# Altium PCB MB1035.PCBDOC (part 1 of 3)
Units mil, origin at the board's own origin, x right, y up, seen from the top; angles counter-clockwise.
Board outline 2598.43 x 3818.9 mil, 2 copper layers (TOP, Bottom); 145 components, 171 nets, 593 pads, 200 vias.
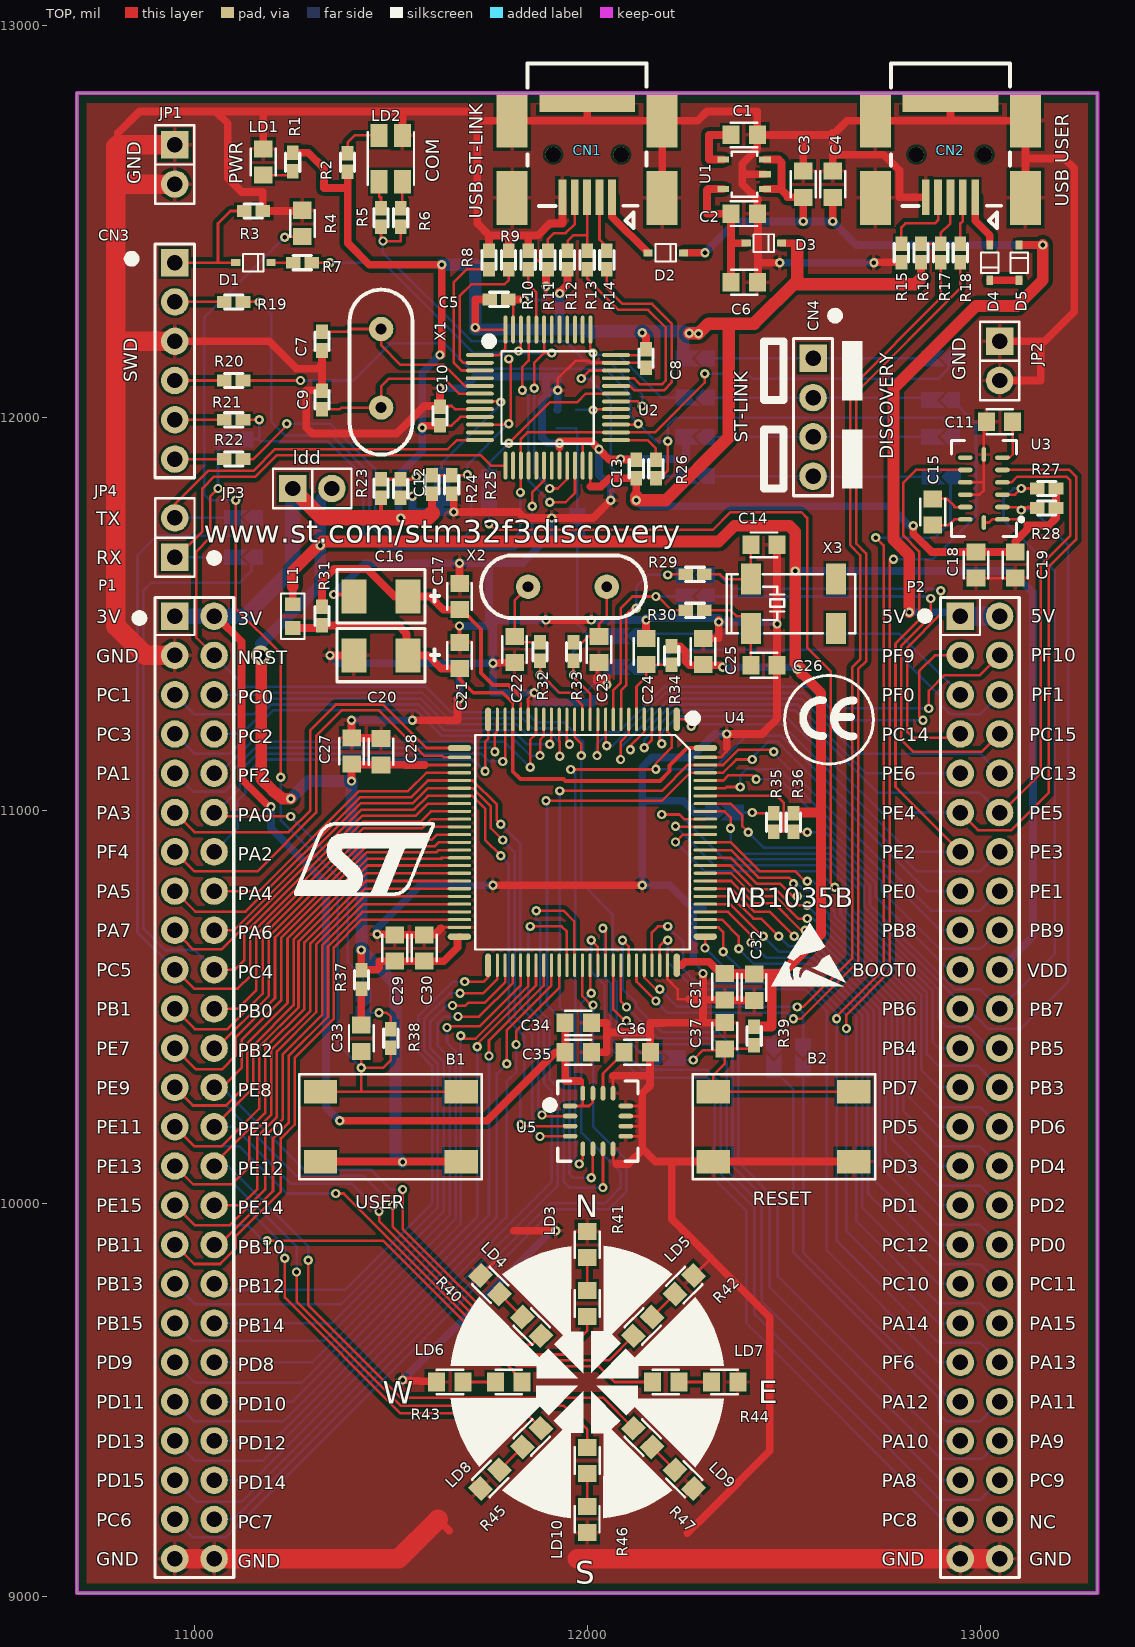
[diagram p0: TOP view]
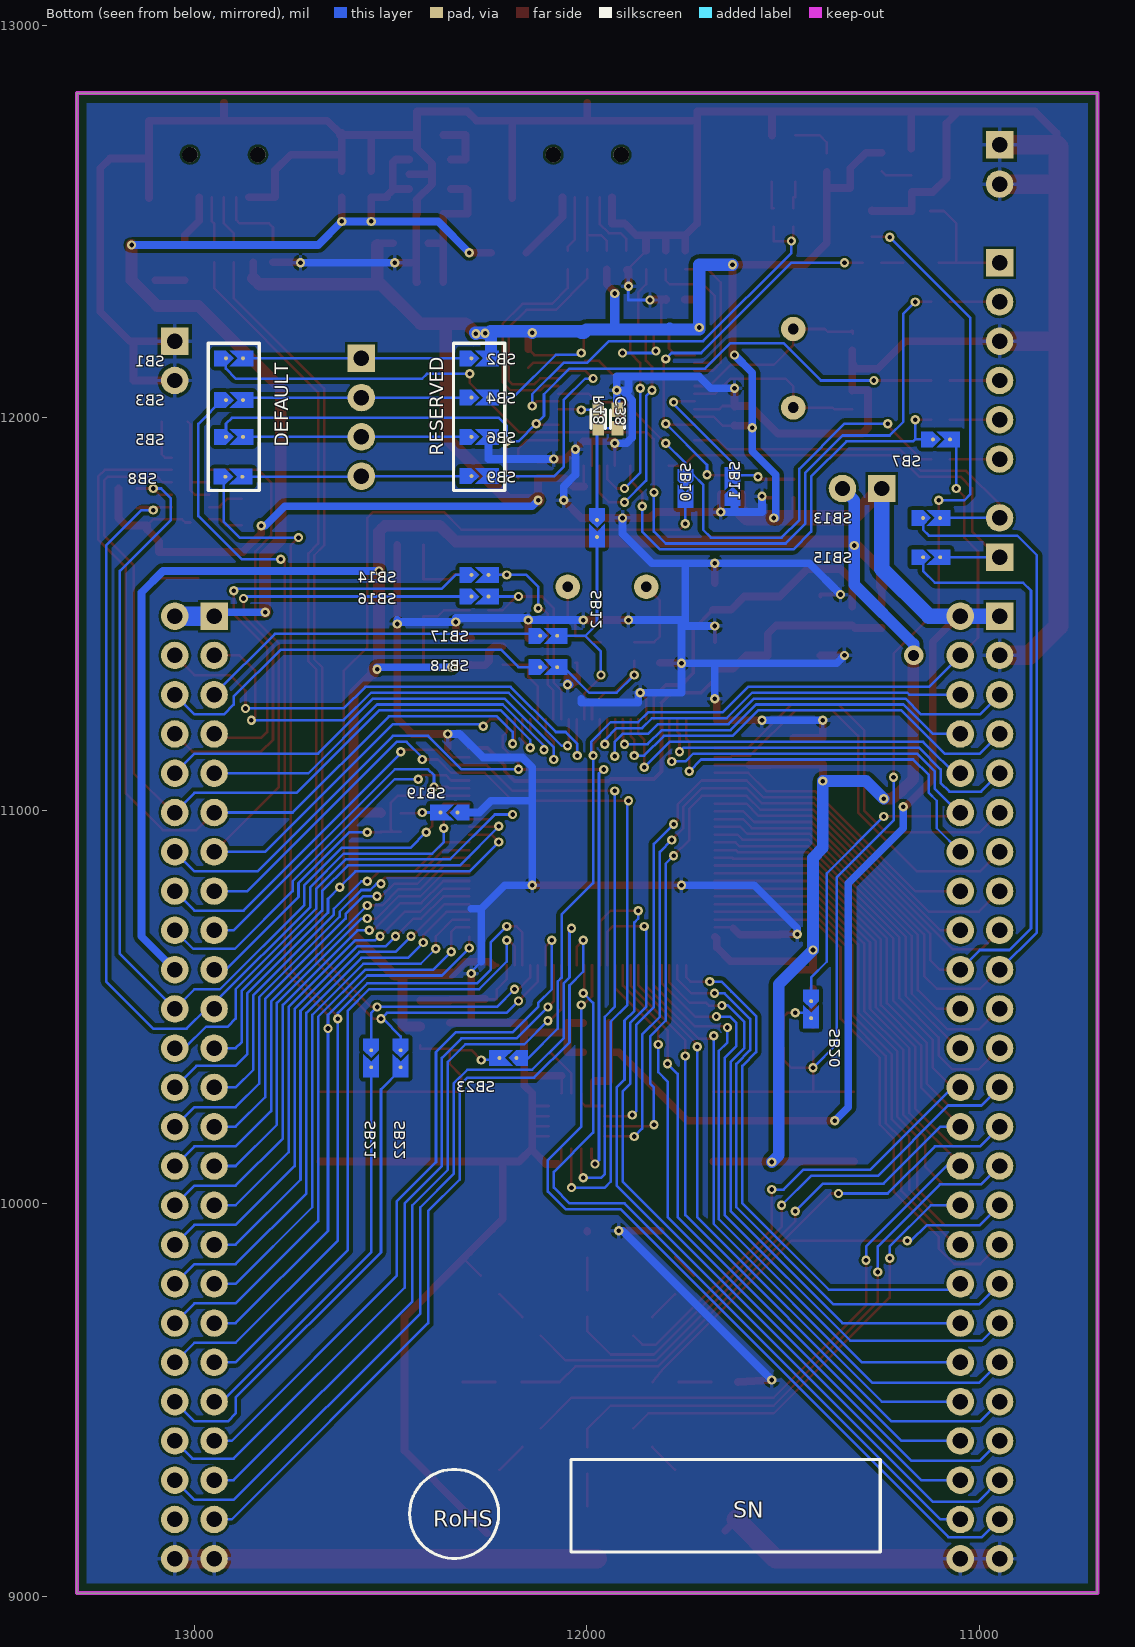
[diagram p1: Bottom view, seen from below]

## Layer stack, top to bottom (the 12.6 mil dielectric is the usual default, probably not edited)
TOP: signal copper (thickness not stored)
Dielectric: dielectric 12.6, FR-4, Dk 4.8
Bottom: signal copper (thickness not stored)

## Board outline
10699.72,9007.52 13298.15,9007.52 13298.15,12826.42 10699.72,12826.42

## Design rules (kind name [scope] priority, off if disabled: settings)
Clearance InPolygon_Template_2 [InNamedPolygon('Template_2') vs InNet('GND')] p1: gap=8.27
Clearance InPolygon_Template_3 [InNamedPolygon('Template_3') vs InNet('GND')] p2: gap=8.27
Clearance CopperToBoard [InPolygon vs (IsTrack Or IsArc) And OnLayer('Keep-out Layer')] p3: gap=19.68
Clearance ViaToCopper [IsVia vs InPolygon] p4: gap=5.91
Clearance ViaToVia [IsVia vs IsVia] p5: gap=5.91
Clearance PadToCopper [IsPad vs InPolygon] p6: gap=5.91
Clearance PadToVia [IsPad vs IsVia] p7: gap=5.91
Clearance PadToPad [IsPad vs IsPad] p8: gap=5.91
Clearance RouteToPad_1 [IsTrack or IsArc vs IsVia] p9: gap=5.91
Clearance RouteToPad [IsTrack Or IsArc vs IsPad] p10: gap=5.91
Clearance RouteToRoute [IsTrack or IsArc vs IsTrack or IsArc] p11: gap=5.91
Clearance [All] p12: gap=10
PolygonConnect [All] p1: connectstyle=Relief reliefconductorwidth=10 reliefentries=4 polygonreliefangle="90 Angle"
RoutingVias [All] p1: holewidth=28 width=50 viastyle="Through Hole" minholewidth=28 minwidth=50 maxholewidth=28 maxwidth=50
SilkscreenOverComponentPads [All] p1: minsilkscreentomaskgap=10
SolderMaskExpansion [All] p1: expansion=4
Width [All] p1: maxlimit=10 minlimit=10 preferedwidth=10
27 further rules are at their usual default settings.

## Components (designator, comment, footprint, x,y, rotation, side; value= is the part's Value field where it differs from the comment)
B1 "Comment" "BP1CMS (Primary)" 11498.93,10194.92 r90 top
B2 "Comment" "BP1CMS (Primary)" 12498.93,10194.92 r270 top
C1 "Comment" "0603C (Primary)" 12398.58,12720.12 r180 top
C2 "Comment" "0603C (Primary)" 12398.58,12519.8 r180 top
C3 "Comment" "0603C (Primary)" 12548.82,12594.92 r270 top
C4 "Comment" "0603C (Primary)" 12623.93,12594.92 r270 top
C5 "Comment" "0402C (Primary)" 11773.93,12301.42 r270 top
C6 "Comment" "0603C (Primary)" 12398.58,12344.8 r0 top
C7 "Comment" "0402C (Primary)" 11323.93,12194.92 r180 top
C8 "Comment" "0402C (Primary)" 12148.93,12151.42 r0 top
C9 "Comment" "0402C (Primary)" 11323.93,12044.92 r0 top
C10 "Comment" "0402C (Primary)" 11623.93,12004.92 r0 top
C11 "Comment" "0603C (Primary)" 13048.93,11989.92 r0 top
C12 "Comment" "0402C (Primary)" 11523.93,11819.92 r180 top
C13 "Comment" "0402C (Primary)" 12123.93,11869.92 r0 top
C14 "Comment" "0603C (Primary)" 12448.93,11676.42 r0 top
C15 "Comment" "0603C (Primary)" 12878.93,11759.92 r90 top
C16 "Comment" "TAN-B (Primary)" 11473.93,11544.92 r180 top
C17 "Comment" "0603C (Primary)" 11673.93,11544.92 r270 top
C18 "Comment" "0603C (Primary)" 12988.93,11624.92 r90 top
C19 "Comment" "0603C (Primary)" 13088.93,11624.92 r90 top
C20 "Comment" "TAN-B (Primary)" 11473.93,11394.92 r180 top
C21 "Comment" "0603C (Primary)" 11673.93,11394.92 r270 top
C22 "Comment" "0603C (Primary)" 11813.93,11409.92 r90 top
C23 "Comment" "0603C (Primary)" 12028.93,11409.92 r90 top
C24 "Comment" "0603C (Primary)" 12148.93,11404.92 r90 top
C25 "Comment" "0603C (Primary)" 12293.93,11404.92 r270 top
C26 "Comment" "0603C (Primary)" 12448.93,11369.92 r0 top
C27 "Comment" "0603C (Primary)" 11398.93,11151.42 r270 top
C28 "Comment" "0603C (Primary)" 11473.93,11149.92 r270 top
C29 "Comment" "0603C (Primary)" 11508.93,10649.92 r270 top
C30 "Comment" "0603C (Primary)" 11583.93,10649.92 r270 top
C31 "Comment" "0603C (Primary)" 12348.93,10551.42 r270 top
C32 "Comment" "0603C (Primary)" 12423.93,10549.92 r270 top
C33 "Comment" "0603C (Primary)" 11423.93,10419.92 r90 top
C34 "Comment" "0603C (Primary)" 11976.34,10459.28 r180 top
C35 "Comment" "0603C (Primary)" 11976.34,10384.28 r180 top
C36 "Comment" "0603C (Primary)" 12126.34,10384.28 r180 top
C37 "Comment" "0603C (Primary)" 12348.93,10426.42 r270 top
C38 "Comment" "0402C (Primary)" 11921.93,11996.92 r0 bottom
CN1 "Comment" "USB-MINI-B-SMD (Primary2)" 11998.93,12669.92 r0 top
CN2 "Comment" "USB-MINI-B-SMD (Primary2)" 12923.93,12669.92 r0 top
CN3 "Comment" "HEADER6/2.54 (Primary)" 10948.93,12394.92 r270 top
CN4 "Comment" "Header 4 (Primary)" 12573.93,12151.42 r270 top
D1 "Comment" "SOD323/A (Primary)" 11148.93,12394.92 r180 top
D2 "Comment" "SOD323/A (Primary)" 12198.93,12419.92 r180 top
D3 "Comment" "SOD323/A (Primary)" 12448.66,12444.69 r180 top
D4 "Comment" "SOD323/A (Primary)" 13023.93,12394.92 r90 top
D5 "Comment" "SOD323/A (Primary)" 13098.93,12394.92 r270 top
JP1 "Comment" "SIP2/2.54 (Primary)" 10948.93,12694.92 r270 top
JP2 "Comment" "SIP2/2.54 (Primary)" 13048.93,12194.92 r270 top
JP3 "Comment" "SIP2/2.54 (Primary)" 11248.93,11819.92 r0 top
JP4 "Comment" "SIP2/2.54 (Primary)" 10948.93,11644.92 r90 top
L1 "Comment" "0603L (Primary)" 11248.93,11494.92 r270 top
LD1 "Comment" "0603D (Primary)" 11173.93,12651.42 r90 top
LD2 "Comment" "HSMF-A201 (Primary)" 11498.93,12659.92 r270 top
LD3 "Comment" "0603D (Primary)" 11998.93,9894.92 r90 top
LD4 "Comment" "0603D (Primary)" 11751.45,9792.41 r135 top
LD5 "Comment" "0603D (Primary)" 12246.42,9792.41 r45 top
LD6 "Comment" "0603D (Primary)" 11648.93,9544.92 r180 top
LD7 "Comment" "0603D (Primary)" 12348.93,9544.92 r0 top
LD8 "Comment" "0603D (Primary)" 11751.45,9297.44 r225 top
LD9 "Comment" "0603D (Primary)" 12246.42,9297.44 r315 top
LD10 "Comment" "0603D (Primary)" 11998.93,9194.92 r270 top
P1 "Comment" "HEAD25X2/2.54 (Primary)" 10998.93,10294.92 r270 top
P2 "Comment" "HEAD25X2/2.54 (Primary)" 12998.93,10294.92 r270 top
R1 "Comment" "0402R (Primary)" 11249.05,12651.42 r180 top
R2 "Comment" "0402R (Primary)" 11388.93,12649.92 r0 top
R3 "Comment" "0402R (Primary)" 11148.93,12526.42 r90 top
R4 "Comment" "0603R (Primary)" 11273.93,12494.92 r270 top
R5 "Comment" "0402R (Primary)" 11473.93,12509.92 r180 top
R6 "Comment" "0402R (Primary)" 11523.97,12509.69 r180 top
R7 "Comment" "0402R (Primary)" 11273.93,12394.92 r90 top
R8 "Comment" "0402R (Primary)" 11748.93,12401.42 r0 top
R9 "Comment" "0402R (Primary)" 11798.93,12401.42 r0 top
R10 "Comment" "0402R (Primary)" 11848.93,12401.42 r0 top
R11 "Comment" "0402R (Primary)" 11898.93,12401.42 r0 top
R12 "Comment" "0402R (Primary)" 11948.93,12401.42 r0 top
R13 "Comment" "0402R (Primary)" 11998.93,12401.42 r0 top
R14 "Comment" "0402R (Primary)" 12048.93,12401.42 r0 top
R15 "Comment" "0402R (Primary)" 12798.93,12419.92 r0 top
R16 "Comment" "0402R (Primary)" 12848.93,12419.92 r0 top
R17 "Comment" "0402R (Primary)" 12898.93,12419.92 r0 top
R18 "Comment" "0402R (Primary)" 12948.93,12419.92 r0 top
R19 "Comment" "0402R (Primary)" 11098.93,12294.92 r90 top
R20 "Comment" "0402R (Primary)" 11098.93,12094.92 r90 top
R21 "Comment" "0402R (Primary)" 11098.93,11994.92 r90 top
R22 "Comment" "0402R (Primary)" 11098.93,11894.92 r90 top
R23 "Comment" "0402R (Primary)" 11473.93,11819.92 r0 top
R24 "Comment" "0402R (Primary)" 11603.93,11829.92 r180 top
R25 "Comment" "0402R (Primary)" 11653.93,11829.92 r180 top
R26 "Comment" "0402R (Primary)" 12173.93,11869.92 r0 top
R27 "Comment" "0402R (Primary)" 13168.93,11819.92 r270 top
R28 "Comment" "0402R (Primary)" 13168.93,11769.92 r270 top
R29 "Comment" "0402R (Primary)" 12273.93,11601.42 r90 top
R30 "Comment" "0402R (Primary)" 12273.93,11509.92 r90 top
R31 "Comment" "0402R (Primary)" 11323.93,11494.92 r0 top
R32 "Comment" "0402R (Primary)" 11878.93,11404.92 r180 top
R33 "Comment" "0402R (Primary)" 11963.93,11404.92 r180 top
R34 "Comment" "0402R (Primary)" 12213.93,11394.92 r180 top
R35 "Comment" "0402R (Primary)" 12473.93,10969.92 r0 top
R36 "Comment" "0402R (Primary)" 12523.93,10969.92 r0 top
R37 "Comment" "0402R (Primary)" 11423.93,10569.92 r180 top
R38 "Comment" "0402R (Primary)" 11498.93,10419.92 r0 top
R39 "Comment" "0402R (Primary)" 12423.93,10426.42 r180 top
R40 "Comment" "0603R (Primary)" 11857.51,9686.34 r315 top
R41 "Comment" "0603R (Primary)" 11998.93,9744.92 r270 top
R42 "Comment" "0603R (Primary)" 12140.36,9686.34 r225 top
R43 "Comment" "0603R (Primary)" 11798.93,9544.92 r0 top
R44 "Comment" "0603R (Primary)" 12198.93,9544.92 r180 top
R45 "Comment" "0603R (Primary)" 11857.51,9403.5 r45 top
R46 "Comment" "0603R (Primary)" 11998.93,9344.92 r90 top
R47 "Comment" "0603R (Primary)" 12140.36,9403.5 r135 top
R48 "Comment" "0402R (Primary)" 11970.93,11996.42 r180 bottom
SB1 "Comment" "JP2_SMD (Primary)" 12898.93,12151.42 r180 bottom
SB2 "Comment" "JP2_SMD (Primary)" 12273.93,12151.42 r180 bottom
SB3 "Comment" "JP2_SMD (Primary)" 12898.93,12044.92 r180 bottom
SB4 "Comment" "JP2_SMD (Primary)" 12273.93,12051.42 r180 bottom
SB5 "Comment" "JP2_SMD (Primary)" 12898.93,11951.42 r180 bottom
SB6 "Comment" "JP2_SMD (Primary)" 12273.93,11951.42 r180 bottom
SB7 "Comment" "JP2_SMD (Primary)" 11098.93,11944.92 r180 bottom
SB8 "Comment" "JP2_SMD (Primary)" 12900.35,11849.89 r180 bottom
SB9 "Comment" "JP2_SMD (Primary)" 12273.93,11851.42 r180 bottom
SB10 "Comment" "JP2_SMD (Primary)" 11748.93,11819.92 r270 bottom
SB11 "Comment" "JP2_SMD (Primary)" 11628.93,11824.92 r90 bottom
SB12 "Comment" "JP2_SMD (Primary)" 11973.93,11719.92 r270 bottom
SB13 "Comment" "JP2_SMD (Primary)" 11123.93,11744.92 r180 bottom
SB14 "Comment" "JP2_SMD (Primary)" 12273.93,11599.92 r180 bottom
SB15 "Comment" "JP2_SMD (Primary)" 11123.93,11644.92 r180 bottom
SB16 "Comment" "JP2_SMD (Primary)" 12273.93,11544.92 r180 bottom
SB17 "Comment" "JP2_SMD (Primary)" 12098.93,11444.92 r180 bottom
SB18 "Comment" "JP2_SMD (Primary)" 12098.93,11364.92 r180 bottom
SB19 "Comment" "JP2_SMD (Primary)" 12348.93,10994.92 r0 bottom
SB20 "Comment" "JP2_SMD (Primary)" 11428.93,10494.92 r270 bottom
SB21 "Comment" "JP2_SMD (Primary)" 12548.93,10369.92 r270 bottom
SB22 "Comment" "JP2_SMD (Primary)" 12473.93,10369.92 r270 bottom
SB23 "Comment" "JP2_SMD (Primary)" 12198.93,10369.92 r0 bottom
U1 "Comment" "SOT-23-5L (Primary)" 12398.58,12619.96 r180 top
U2 "Comment" "LQFP48 (Primary)" 11898.93,12051.42 r0 top
U3 "Comment" "LGA14 (Primary)" 13008.93,11819.92 r180 top
U4 "Comment" "QFP100-1414 (Primary)" 11986.69,10919.03 r180 top
U5 "Comment" "LGA16 (Primary)" 12026.34,10209.28 r0 top
X1 "Comment" "XTAL1 (Primary)" 11473.93,12026.42 r90 top
X2 "Comment" "XTAL1 (Primary)" 11848.93,11569.92 r0 top
X3 "Comment" "MC306-CRYSTAL (Primary)" 12523.93,11526.42 r0 top

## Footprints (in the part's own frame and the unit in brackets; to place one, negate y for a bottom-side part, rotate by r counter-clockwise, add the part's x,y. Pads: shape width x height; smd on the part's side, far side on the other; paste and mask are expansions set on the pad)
"0402C (Primary)" [mil]
  rect 30x37 smd paste-3.94 mask+0: 1(0,23.62) 2(0,-23.62)
  silkscreen extent -18,-23 18,24
"0402R (Primary)" [mil]
  rect 30x37 smd paste-3.94 mask+0: 1(0,23.62) 2(0,-23.62)
  silkscreen extent -18,-23 18,24
"0603C (Primary)" [mm]
  rect 1.1x1.2 smd paste-0.1 mask+0: 1(-0.85,0) 2(0.85,0)
  silkscreen extent -0.85,-0.8 0.86,0.8
"0603D (Primary)" [mm]
  rect 1.1x1.2 smd paste-0.1 mask+0: 1(-0.85,0) 2(0.85,0)
  silkscreen extent -0.86,-0.8 0.84,0.8
"0603L (Primary)" [mil]
  rect 35x40 smd paste-3.94 mask+0: 1(-30,0) 2(30,0)
  silkscreen extent -58,-30 58,30
"0603R (Primary)" [mm]
  rect 1.1x1.2 smd paste-0.1 mask+0: 1(-0.85,0) 2(0.85,0)
  silkscreen extent -0.85,-0.8 0.86,0.8
"BP1CMS (Primary)" [mm]
  rect 1.52x2.16 smd paste-0.1 mask+0: 1(-2.25,-4.55) 2(-2.25,4.55) 3(2.25,-4.55) 4(2.25,4.55)
  silkscreen extent -3.4,-5.88 3.4,5.92
"HEAD25X2/2.54 (Primary)" [mil]
  rect 70x70 / inner round 60 / far side rect 70x70 hole 39.37 paste+0 mask+0: 1(-1200,-50)
  round 70 / inner round 60 / far side round 70 hole 39.37 paste+0 mask+0: 2(-1200,50) 3(-1100,-50) 4(-1100,50) 5(-1000,-50) 6(-1000,50) 7(-900,-50) 8(-900,50) 9(-800,-50) 10(-800,50) 11(-700,-50) 12(-700,50) 13(-600,-50) 14(-600,50) 15(-500,-50) 16(-500,50) 17(-400,-50) 18(-400,50) 19(-300,-50) 20(-300,50) 21(-200,-50) 22(-200,50) 23(-100,-50) 24(-100,50) 25(0,-50) 26(0,50) 27(100,-50) 28(100,50) 29(200,-50) 30(200,50) 31(300,-50) 32(300,50) 33(400,-50) 34(400,50) 35(500,-50) 36(500,50) 37(600,-50) 38(600,50) 39(700,-50) 40(700,50) 41(800,-50) 42(800,50) 43(900,-50) 44(900,50) 45(1000,-50) 46(1000,50) 47(1100,-50) 48(1100,50) 49(1200,-50) 50(1200,50)
  silkscreen extent -1248,-101 1248,100
"HEADER6/2.54 (Primary)" [mil]
  rect 70x70 / inner round 60 / far side rect 70x70 hole 39.37 paste+0 mask+0: 1(0,0)
  round 70 / inner round 60 / far side round 70 hole 39.37 paste+0 mask+0: 2(100,0) 3(200,0) 4(300,0) 5(400,0) 6(500,0)
  silkscreen extent -48,-50 548,50
"Header 4 (Primary)" [mil]
  rect 70x70 / inner round 60 / far side rect 70x70 hole 39.37 paste+0 mask+0: 1(0,0)
  round 70 / inner round 60 / far side round 70 hole 39.37 paste+0 mask+0: 2(100,0) 3(200,0) 4(300,0)
  silkscreen extent -50,-50 350,50
"HSMF-A201 (Primary)" [mm]
  rect 1.5x1.1 smd paste-0.1 mask+0: 1(-1.5,0.75) 2(1.5,0.75) 3(1.5,-0.75) 4(-1.5,-0.75)
  silkscreen extent -1.7,-1.5 1.7,1.5
"JP2_SMD (Primary)" [mil]
  round 10 smd paste-3.94 mask+0: 1(-19.68,0) 2(23.62,0)
  TOP region: -19.68,19.68 -49.21,19.68 -49.21,-19.69 -19.68,-19.69 0,0
  TOP region: -9.84,-19.69 49.21,-19.69 49.21,19.68 -9.84,19.68 9.84,0
"LGA14 (Primary)" [mm]
  oval 0.95x0.3 smd paste-0.1 mask+0: 1(-1.2,2) 2(-1.2,1.2) 3(-1.2,0.4) 4(-1.2,-0.4) 5(-1.2,-1.2) 6(-1.2,-2) 8(1.2,-2) 9(1.2,-1.2) 10(1.2,-0.4) 11(1.2,0.4) 12(1.2,1.2) 13(1.2,2)
  oval 0.3x0.95 smd paste-0.1 mask+0: 7(0,-2.2) 14(0,2.2)
  silkscreen extent -2.55,-3.1 2.1,3.1
"LGA16 (Primary)" [mm]
  oval 0.95x0.3 smd paste-0.1 mask+0: 1(-1.8,0.975) 2(-1.8,0.325) 3(-1.8,-0.325) 4(-1.8,-0.975) 9(1.8,-0.975) 10(1.8,-0.325) 11(1.8,0.325) 12(1.8,0.975)
  oval 0.3x0.95 smd paste-0.1 mask+0: 5(-0.975,-1.8) 6(-0.325,-1.8) 7(0.325,-1.8) 8(0.975,-1.8) 13(0.975,1.8) 14(0.325,1.8) 15(-0.325,1.8) 16(-0.975,1.8)
  silkscreen extent -3.18,-2.6 2.6,2.6
"LQFP48 (Primary)" [mm]
  oval 1.803x0.257 smd paste-0.1 mask+0: 1(-4.4,2.75) 12(-4.4,-2.75) 25(4.4,-2.75) 36(4.4,2.75)
  oval 1.803x0.254 smd paste-0.1 mask+0: 2(-4.4,2.25) 3(-4.4,1.75) 4(-4.4,1.25) 5(-4.4,0.75) 6(-4.4,0.25) 7(-4.4,-0.25) 8(-4.4,-0.75) 9(-4.4,-1.25) 10(-4.4,-1.75) 11(-4.4,-2.25) 26(4.4,-2.25) 27(4.4,-1.75) 28(4.4,-1.25) 29(4.4,-0.75) 30(4.4,-0.25) 31(4.4,0.25) 32(4.4,0.75) 33(4.4,1.25) 34(4.4,1.75) 35(4.4,2.25)
  oval 0.257x1.803 smd paste-0.1 mask+0: 13(-2.75,-4.4) 24(2.75,-4.4) 37(2.75,4.4) 48(-2.75,4.4)
  oval 0.254x1.803 smd paste-0.1 mask+0: 14(-2.25,-4.4) 15(-1.75,-4.4) 16(-1.25,-4.4) 17(-0.75,-4.4) 18(-0.25,-4.4) 19(0.25,-4.4) 20(0.75,-4.4) 21(1.25,-4.4) 22(1.75,-4.4) 23(2.25,-4.4) 38(2.25,4.4) 39(1.75,4.4) 40(1.25,4.4) 41(0.75,4.4) 42(0.25,4.4) 43(-0.25,4.4) 44(-0.75,4.4) 45(-1.25,4.4) 46(-1.75,4.4) 47(-2.25,4.4)
  silkscreen extent -3.87,-2.98 2.97,3.83
"MC306-CRYSTAL (Primary)" [mm]
  rect 1.3x2 smd paste-0.1 mask+0: 1(-2.75,-1.6) 2(2.75,-1.6) 3(2.75,1.6) 4(-2.75,1.6)
  silkscreen extent -4.3,-1.9 4,1.9
"QFP100-1414 (Primary)" [mil]
  oval 16x60 smd paste-3.94 mask+0: 1(-240.16,-312.99) 25(240.16,-312.99) 51(240.16,312.99) 75(-240.16,312.99)
  oval 8x60 smd paste-3.94 mask+0: 2(-216.54,-312.99) 3(-196.85,-312.99) 4(-177.17,-312.99) 5(-157.48,-312.99) 6(-137.8,-312.99) 7(-118.11,-312.99) 8(-98.43,-312.99) 9(-78.74,-312.99) 10(-59.06,-312.99) 11(-39.37,-312.99) 12(-19.68,-312.99) 13(0,-312.99) 14(19.69,-312.99) 15(39.37,-312.99) 16(59.06,-312.99) 17(78.74,-312.99) 18(98.43,-312.99) 19(118.11,-312.99) 20(137.8,-312.99) 21(157.48,-312.99) 22(177.17,-312.99) 23(196.85,-312.99) 24(216.54,-312.99) 52(216.54,312.99) 53(196.85,312.99) 54(177.17,312.99) 55(157.48,312.99) 56(137.8,312.99) 57(118.11,312.99) 58(98.43,312.99) 59(78.74,312.99) 60(59.06,312.99) 61(39.37,312.99) 62(19.69,312.99) 63(0,312.99) 64(-19.68,312.99) 65(-39.37,312.99) 66(-59.06,312.99) 67(-78.74,312.99) 68(-98.43,312.99) 69(-118.11,312.99) 70(-137.8,312.99) 71(-157.48,312.99) 72(-177.17,312.99) 73(-196.85,312.99) 74(-216.54,312.99)
  oval 60x16 smd paste-3.94 mask+0: 26(312.99,-240.16) 50(312.99,240.16) 76(-312.99,240.16) 100(-312.99,-240.16)
  oval 60x8 smd paste-3.94 mask+0: 27(312.99,-216.54) 28(312.99,-196.85) 29(312.99,-177.17) 30(312.99,-157.48) 31(312.99,-137.8) 32(312.99,-118.11) 33(312.99,-98.43) 34(312.99,-78.74) 35(312.99,-59.06) 36(312.99,-39.37) 37(312.99,-19.68) 38(312.99,0) 39(312.99,19.69) 40(312.99,39.37) 41(312.99,59.06) 42(312.99,78.74) 43(312.99,98.43) 44(312.99,118.11) 45(312.99,137.8) 46(312.99,157.48) 47(312.99,177.17) 48(312.99,196.85) 49(312.99,216.54) 77(-312.99,216.54) 78(-312.99,196.85) 79(-312.99,177.17) 80(-312.99,157.48) 81(-312.99,137.8) 82(-312.99,118.11) 83(-312.99,98.43) 84(-312.99,78.74) 85(-312.99,59.06) 86(-312.99,39.37) 87(-312.99,19.69) 88(-312.99,0) 89(-312.99,-19.68) 90(-312.99,-39.37) 91(-312.99,-59.06) 92(-312.99,-78.74) 93(-312.99,-98.43) 94(-312.99,-118.11) 95(-312.99,-137.8) 96(-312.99,-157.48) 97(-312.99,-177.17) 98(-312.99,-196.85) 99(-312.99,-216.54)
  silkscreen extent -285,-328 273,273
"SIP2/2.54 (Primary)" [mil]
  rect 70x70 / inner round 60 / far side rect 70x70 hole 39.37 paste+0 mask+0: 1(0,0)
  round 70 / inner round 60 / far side round 70 hole 39.37 paste+0 mask+0: 2(100,0)
  silkscreen extent -50,-50 150,50
"SOD323/A (Primary)" [mm]
  rect 0.6x0.45 smd paste-0.1 mask+0: 1(1.143,0) 2(-1.143,0)
  silkscreen extent -0.67,-0.57 0.67,0.57
"SOT-23-5L (Primary)" [mil]
  rect 30x16 smd paste-3.94 mask+0: 1(-53.15,37.4) 2(-53.15,0) 3(-53.15,-37.4) 4(53.15,-37.4) 5(53.15,37.4)
  silkscreen extent -33,-58 32,57
"TAN-B (Primary)" [mm]
  rect 1.6x2.2 smd paste-0.1 mask+0: 1(-1.75,0) 2(1.75,0)
  silkscreen extent -3.75,-1.75 2.85,1.7
"USB-MINI-B-SMD (Primary2)" [mm]
  rect 0.508x2.3 smd paste-0.1 mask+0: 1(1.597,-2.75) 2(0.797,-2.75) 3(-0.003,-2.75) 4(-0.803,-2.75) 5(-1.603,-2.75)
  rect 2x3.5 smd paste-0.1 mask+0: 6(-4.853,-2.8) 7(-4.853,2.2) 8(4.847,-2.8) 9(4.847,2.2)
  rect 6.2x1.2 smd paste-0.1 mask+0: 10(0,3.35)
  round 1 / inner round 1.524 / far side round 1 hole 1 unplated paste+0 mask+0: 11(2.194,0) 12(-2.2,0)
  silkscreen extent -3.85,-4.76 3.85,5.9
"XTAL1 (Primary)" [mil]
  round 62 / inner round 60 / far side round 62 hole 27.56 paste+0 mask+0: 1(-0.36,-0.2) 2(199.64,-0.2)
  silkscreen extent -120,-80 300,80

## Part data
B1 B2: library part BP1CMS
C1 C2 C3 C4 C6 C11 C14 C15 C17 C18 C19 C21 C22 C23 C24 C25 C26 C27 C28 C29 C30 C31 C32 C33 C34 C35 C36 C37: library part 0603C
C5 C7 C8 C9 C10 C12 C13 C38: library part 0402C
C16 C20: library part TAN-B
CN3: library part HEADER6_2.54
CN4: library part HEADER_4
D1 D2 D3 D4 D5: library part SOD323_A
JP1 JP2 JP3 JP4: library part SIP2_2.54
L1: library part 0603L
LD1 LD3 LD4 LD5 LD6 LD7 LD8 LD9 LD10: library part 0603D
LD2: library part HSMF-A201
P1 P2: library part HEAD25X2_2.54
R1 R2 R3 R5 R6 R7 R8 R9 R10 R11 R12 R13 R14 R15 R16 R17 R18 R19 R20 R21 R22 R23 R24 R25 R26 R27 R28 R29 R30 R31 R32 R33 R34 R35 R36 R37 R38 R39 R48: library part 0402R
R4 R40 R41 R42 R43 R44 R45 R46 R47: library part 0603R
SB1 SB2 SB3 SB4 SB5 SB6 SB7 SB8 SB9 SB10 SB11 SB12 SB13 SB14 SB15 SB16 SB17 SB18 SB19 SB20 SB21 SB22 SB23: library part JP2_SMD
U1: library part SOT-23-5L
U2: library part LQFP48
U3: library part LGA14
U4: library part QFP100-1414
U5: library part LGA16
X1 X2: library part XTAL1
X3: library part MC306-CRYSTAL

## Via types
v1: diameter 23.62, hole 11.81, TOP to Bottom, 199 vias
v2: diameter 50, hole 27.56, TOP to Bottom, 1 vias

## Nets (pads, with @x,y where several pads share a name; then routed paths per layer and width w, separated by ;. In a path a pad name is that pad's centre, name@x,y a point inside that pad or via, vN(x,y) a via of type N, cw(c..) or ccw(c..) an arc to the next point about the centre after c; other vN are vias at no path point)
3V: C5.2 C8.1 C10.2 C13.2 C18.2 C19.2 C34.2 C35.2 D3.2 JP3.1 P1.1 P1.2 R1.2 R2.2 R12.2 R16.2 R23.2 R24.1 R27.1 R28.1 SB2.2 U2.1 U2.9 U2.24 U2.36 U2.48 U3.1 U3.14 U5.1 U5.15 U5.16 | length 9585.9
  TOP w6.5: 11473.93,11744.92 11473.93,11754.92 ; C10.2@11623.93,11979.92 11653.93,11979.92 11676.22,12002.21 U2.9@11725.71,12002.21 ; v1@11718.14,12226.42 11719.91,12224.65 U2.48@11790.67,12224.65 11790.67,12176.42 11773.93,12159.69 U2.1@11725.71,12159.69 ; U5.1@11955.48,10247.66 11987.96,10247.66 ; 11980.55,10311.07 11987.96,10311.07 U5.16@11987.96,10280.14 11987.96,10247.66 ; 12007.2,11824.92 U2.24@12007.2,11878.19 ; U5.15@12013.55,10280.14 12013.55,10257.28 12003.93,10247.66 11987.96,10247.66 ; U2.36@12072.17,12159.69 12133.58,12159.69 C8.1@12148.93,12175.04 ; U3.14@13008.93,11733.31 13022.32,11733.31 13030.19,11741.18 U3.1@13056.18,11741.18 13103.93,11741.18 13119.56,11725.55
  TOP w9.84: 11473.93,11754.92 R23.2@11473.93,11796.3
  TOP w19.68: P1.2@11048.93,11494.92 11053.93,11494.92 11118.93,11429.92 11118.93,11079.92 11188.93,11009.92 v1(11193.93,11009.92) ; R1.2@11249.05,12675.04 11288.93,12675.04 11328.93,12635.04 11328.93,12584.92 11388.93,12584.92 ; v1(11368.93,10209.92) 11743.93,10209.92 11918.29,10384.28 C35.2@11942.88,10384.28 C34.2@11942.88,10459.28 ; R2.2@11388.93,12626.3 11388.93,12584.92 ; v1(11578.93,11974.92) 11578.93,11979.92 11623.93,11979.92 C10.2@11623.93,11981.3 ; 11603.93,11756.9 R24.1@11603.93,11806.3 ; v1(11623.93,12159.92) 11628.93,12159.92 v1(11628.93,12389.92) 11443.93,12389.92 11388.93,12444.92 11388.93,12584.92 ; v1(11713.93,12229.92) 11713.93,12226.42 11718.14,12226.42 11713.93,12230.62 11713.93,12301.42 C5.2@11750.31,12301.42 ; v1@11928.93,12319.92 11948.93,12339.92 R12.2@11948.93,12377.8 ; 12007.2,11824.92 12033.93,11824.92 12055.31,11846.3 C13.2@12123.93,11846.3 v1@12123.93,11799.92 ; v1(12138.93,12216.42) 12148.93,12206.42 C8.1@12148.93,12175.04 ; D3.2@12493.66,12444.69 12533.93,12444.69 12533.93,12439.92 ; v1(12828.93,11724.92) 12828.93,11704.92 12875.47,11658.39 C18.2@12988.93,11658.39 C19.2@13088.93,11658.39 13088.93,11684.92 13119.56,11715.55 13119.56,11725.55 13173.19,11725.55 13192.56,11744.92 R28.1@13192.56,11769.92 R27.1@13192.56,11819.92 ; 12848.93,12354.92 R16.2@12848.93,12396.3
  TOP w20: C35.2@11942.88,10384.28 11942.88,10311.07 11980.55,10311.07
  TOP w23.62: v1(11928.93,12316.42) v1@11928.93,12319.92
  TOP w31.5: v1@12123.93,11799.92 v1(12123.93,11789.92) 12198.93,11789.92 12358.93,11949.92 12358.93,12239.81 ; v1(12258.93,12214.92) 12282.25,12214.92 v1(12282.25,12214.2) 12307.86,12239.81 12358.93,12239.81 ; 12533.93,12439.92 12533.93,12349.81 ; 12848.93,12354.92 12833.93,12339.92 12533.93,12339.92 12533.93,12349.81 ; 12358.93,12239.81 12423.93,12239.81 12533.93,12349.81
  TOP w39.37: JP3.1@11248.93,11819.92 11323.93,11744.92 11473.93,11744.92 v1(11523.93,11744.92) 11591.96,11744.92 11603.93,11756.9
  Bottom w6.5: 11788.93,12226.42 11790.67,12224.69
  Bottom w19.68: v1(11193.93,11009.92) 11193.93,10954.92 11333.93,10814.92 11333.93,10244.92 v1(11368.93,10209.92) ; v1(11523.93,11744.92) 11518.93,11744.92 11518.93,11854.92 11578.93,11914.92 v1(11578.93,11974.92) 11578.93,12114.92 v1(11623.93,12159.92) ; v1(12123.93,11789.92) 12138.93,11774.92 12768.93,11774.92 12818.93,11724.92 v1(12828.93,11724.92)
  Bottom w23.62: 11928.93,12226.42 v1(11928.93,12316.42)
  Bottom w31.5: v1(11628.93,12389.92) 11713.93,12389.92 v1(11713.93,12229.92) 11713.93,12224.92 11788.93,12224.92 11788.93,12226.42 ; 11790.67,12224.69 11790.67,12224.92 11928.93,12224.92 ; 11928.93,12226.42 11928.93,12224.92 ; v1(12138.93,12216.42) v1@12138.93,12219.92 ; SB2.2@12250.31,12151.42 12243.93,12151.42 12243.93,12216.17 12238.93,12216.19 12240.92,12216.19 ; v1(12258.93,12214.92) 12242.18,12214.92 12240.92,12216.19 ; 11928.93,12224.92 12001.73,12224.92 12001.73,12221.42 ; 12001.73,12221.42 12006.97,12216.19 12012.33,12216.19 ; 12001.73,12221.42 12007.1,12221.42 12012.33,12216.19 ; 12012.33,12216.19 12014.53,12216.42 12014.53,12219.92 v1@12138.93,12219.92 ; v1@12138.93,12219.92 12245.2,12219.92 v1@12248.93,12216.19 ; 12240.92,12216.19 v1@12248.93,12216.19 ; v1@12248.93,12216.19 v1@12282.25,12216.19 ; v1@12282.25,12216.19 12284.24,12216.19 v1(12282.25,12214.2) v1@12282.25,12216.19
  Bottom w39.37: P1.1@10958.93,11494.92 P1.2@11038.93,11494.92 ; P1.2@11048.93,11494.92 11128.93,11494.92 11248.93,11614.92 JP3.1@11248.93,11819.92
  Bottom w50: P1.1@10948.93,11494.92 P1.1@10958.93,11494.92 ; P1.2@11038.93,11494.92 P1.2@11048.93,11494.92
5V: C3.2 C4.2 D2.2 D5.2 P2.1 P2.2 U1.1 U1.3 | length 2789.8
  TOP w19.68: D2.2@12243.93,12419.92 v1(12298.93,12419.92) ; U1.1@12451.73,12582.56 12491.3,12582.56 12493.93,12579.92 ; U1.3@12451.73,12657.36 12486.49,12657.36 12493.93,12649.92 12493.93,12579.92 ; v1(12548.93,12499.92) 12548.93,12561.46 C3.2@12548.82,12561.46 12508.93,12561.46 12508.93,12564.92 12493.93,12579.92 ; v1(12623.93,12499.92) C4.2@12623.93,12561.46 ; D5.2@13098.93,12439.92 v1(13158.93,12439.92)
  TOP w30: v1(12818.93,11504.92) 12818.93,11649.92 12778.93,11689.92 12778.93,12074.92 12988.93,12284.92 13093.93,12284.92 13158.93,12349.92 v1(13158.93,12439.92)
  Bottom w19.68: v1(12298.93,12419.92) 12378.93,12499.92 v1(12548.93,12499.92) v1(12623.93,12499.92) 12683.93,12439.92 v1(13158.93,12439.92) ; v1(12818.93,11504.92) 12948.93,11504.92 P2.1@12948.93,11494.92
  Bottom w50: P2.1@12948.93,11494.92 P2.2@13048.93,11494.92
179: P2.42 SB22.2 | length 1239.3
  Bottom w6.5: SB22.2@12473.93,10346.3 12473.93,10339.92 12523.93,10289.92 12523.93,9874.92 12893.93,9504.92 12893.93,9464.92 12913.93,9444.92 12998.93,9444.92 P2.42@13048.93,9494.92
180: P2.41 SB21.2 | length 1028.8
  Bottom w6.5: SB21.2@12548.93,10346.3 12548.93,9874.92 12928.93,9494.92 P2.41@12948.93,9494.92
AIN_1: R7.2 R24.2 R25.2 U2.10 | length 1116.1
  TOP w6.5: R7.2@11297.56,12394.92 v1(11343.93,12394.92) ; R24.2@11603.93,11853.54 R25.2@11653.93,11853.54 11692.56,11853.54 11692.56,11854.92 v1(11693.93,11854.92) ; U2.10@11725.71,11982.53 11786.54,11982.53 11788.93,11984.92 v1@11793.93,11984.92 ; v1(11798.93,11984.92) v1@11793.93,11984.92 ; v1(11798.93,12149.92) 11803.93,12149.92 11803.93,11994.92 v1@11793.93,11984.92
  Bottom w6.5: v1(11343.93,12394.92) 11478.93,12394.92 11708.93,12164.92 11783.93,12164.92 v1(11798.93,12149.92) ; v1(11693.93,11854.92) 11693.93,11879.92 v1(11798.93,11984.92)
BOOT0: P2.19 R35.2 R36.2 U4.94 | length 923.9
  TOP w6.5: U4.94@12299.68,11037.14 12481.72,11037.14 12498.93,11019.92 12498.93,10951.3 12493.93,10946.3 ; R35.2@12473.93,10946.3 12493.93,10946.3 ; v1(12558.93,10944.92) 12523.93,10944.92 R36.2@12523.93,10946.3 12493.93,10946.3
  Bottom w6.5: v1(12558.93,10944.92) 12603.93,10944.92 12733.93,10814.92 12733.93,10779.92 12918.93,10594.92 P2.19@12948.93,10594.92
